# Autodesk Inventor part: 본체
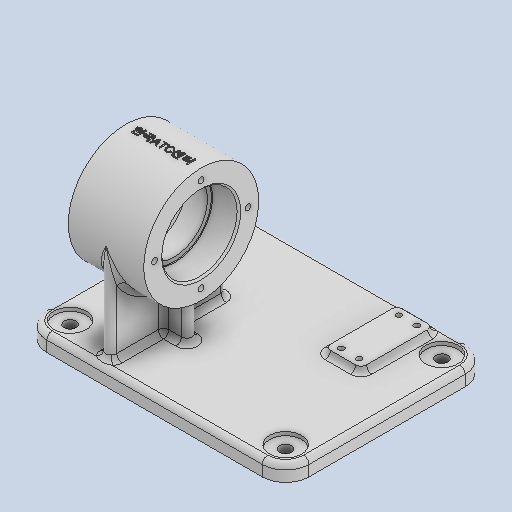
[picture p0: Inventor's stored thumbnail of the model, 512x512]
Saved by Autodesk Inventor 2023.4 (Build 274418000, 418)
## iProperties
Created: 2024-04
Part Number: 본체
Material: 일반
Document SubType Name: Modeling
Designer: EDU
Density: 1 g/cm^3
Appearance: 기본값
Author: jhkim
Sending System: Autodesk Inventor 2025
Preprocessor: ST-DEVELOPER v20
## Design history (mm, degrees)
node "본체1"
node "솔리드2"
node "솔리드1"
